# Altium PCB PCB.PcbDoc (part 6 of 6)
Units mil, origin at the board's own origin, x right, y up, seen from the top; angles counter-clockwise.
Board outline 7100 x 7000 mil, 4 copper layers (Top Layer, GND, VCC, Bottom Layer), stack 61.2 mil thick; 759 components, 507 nets, 2200 pads, 452 vias.
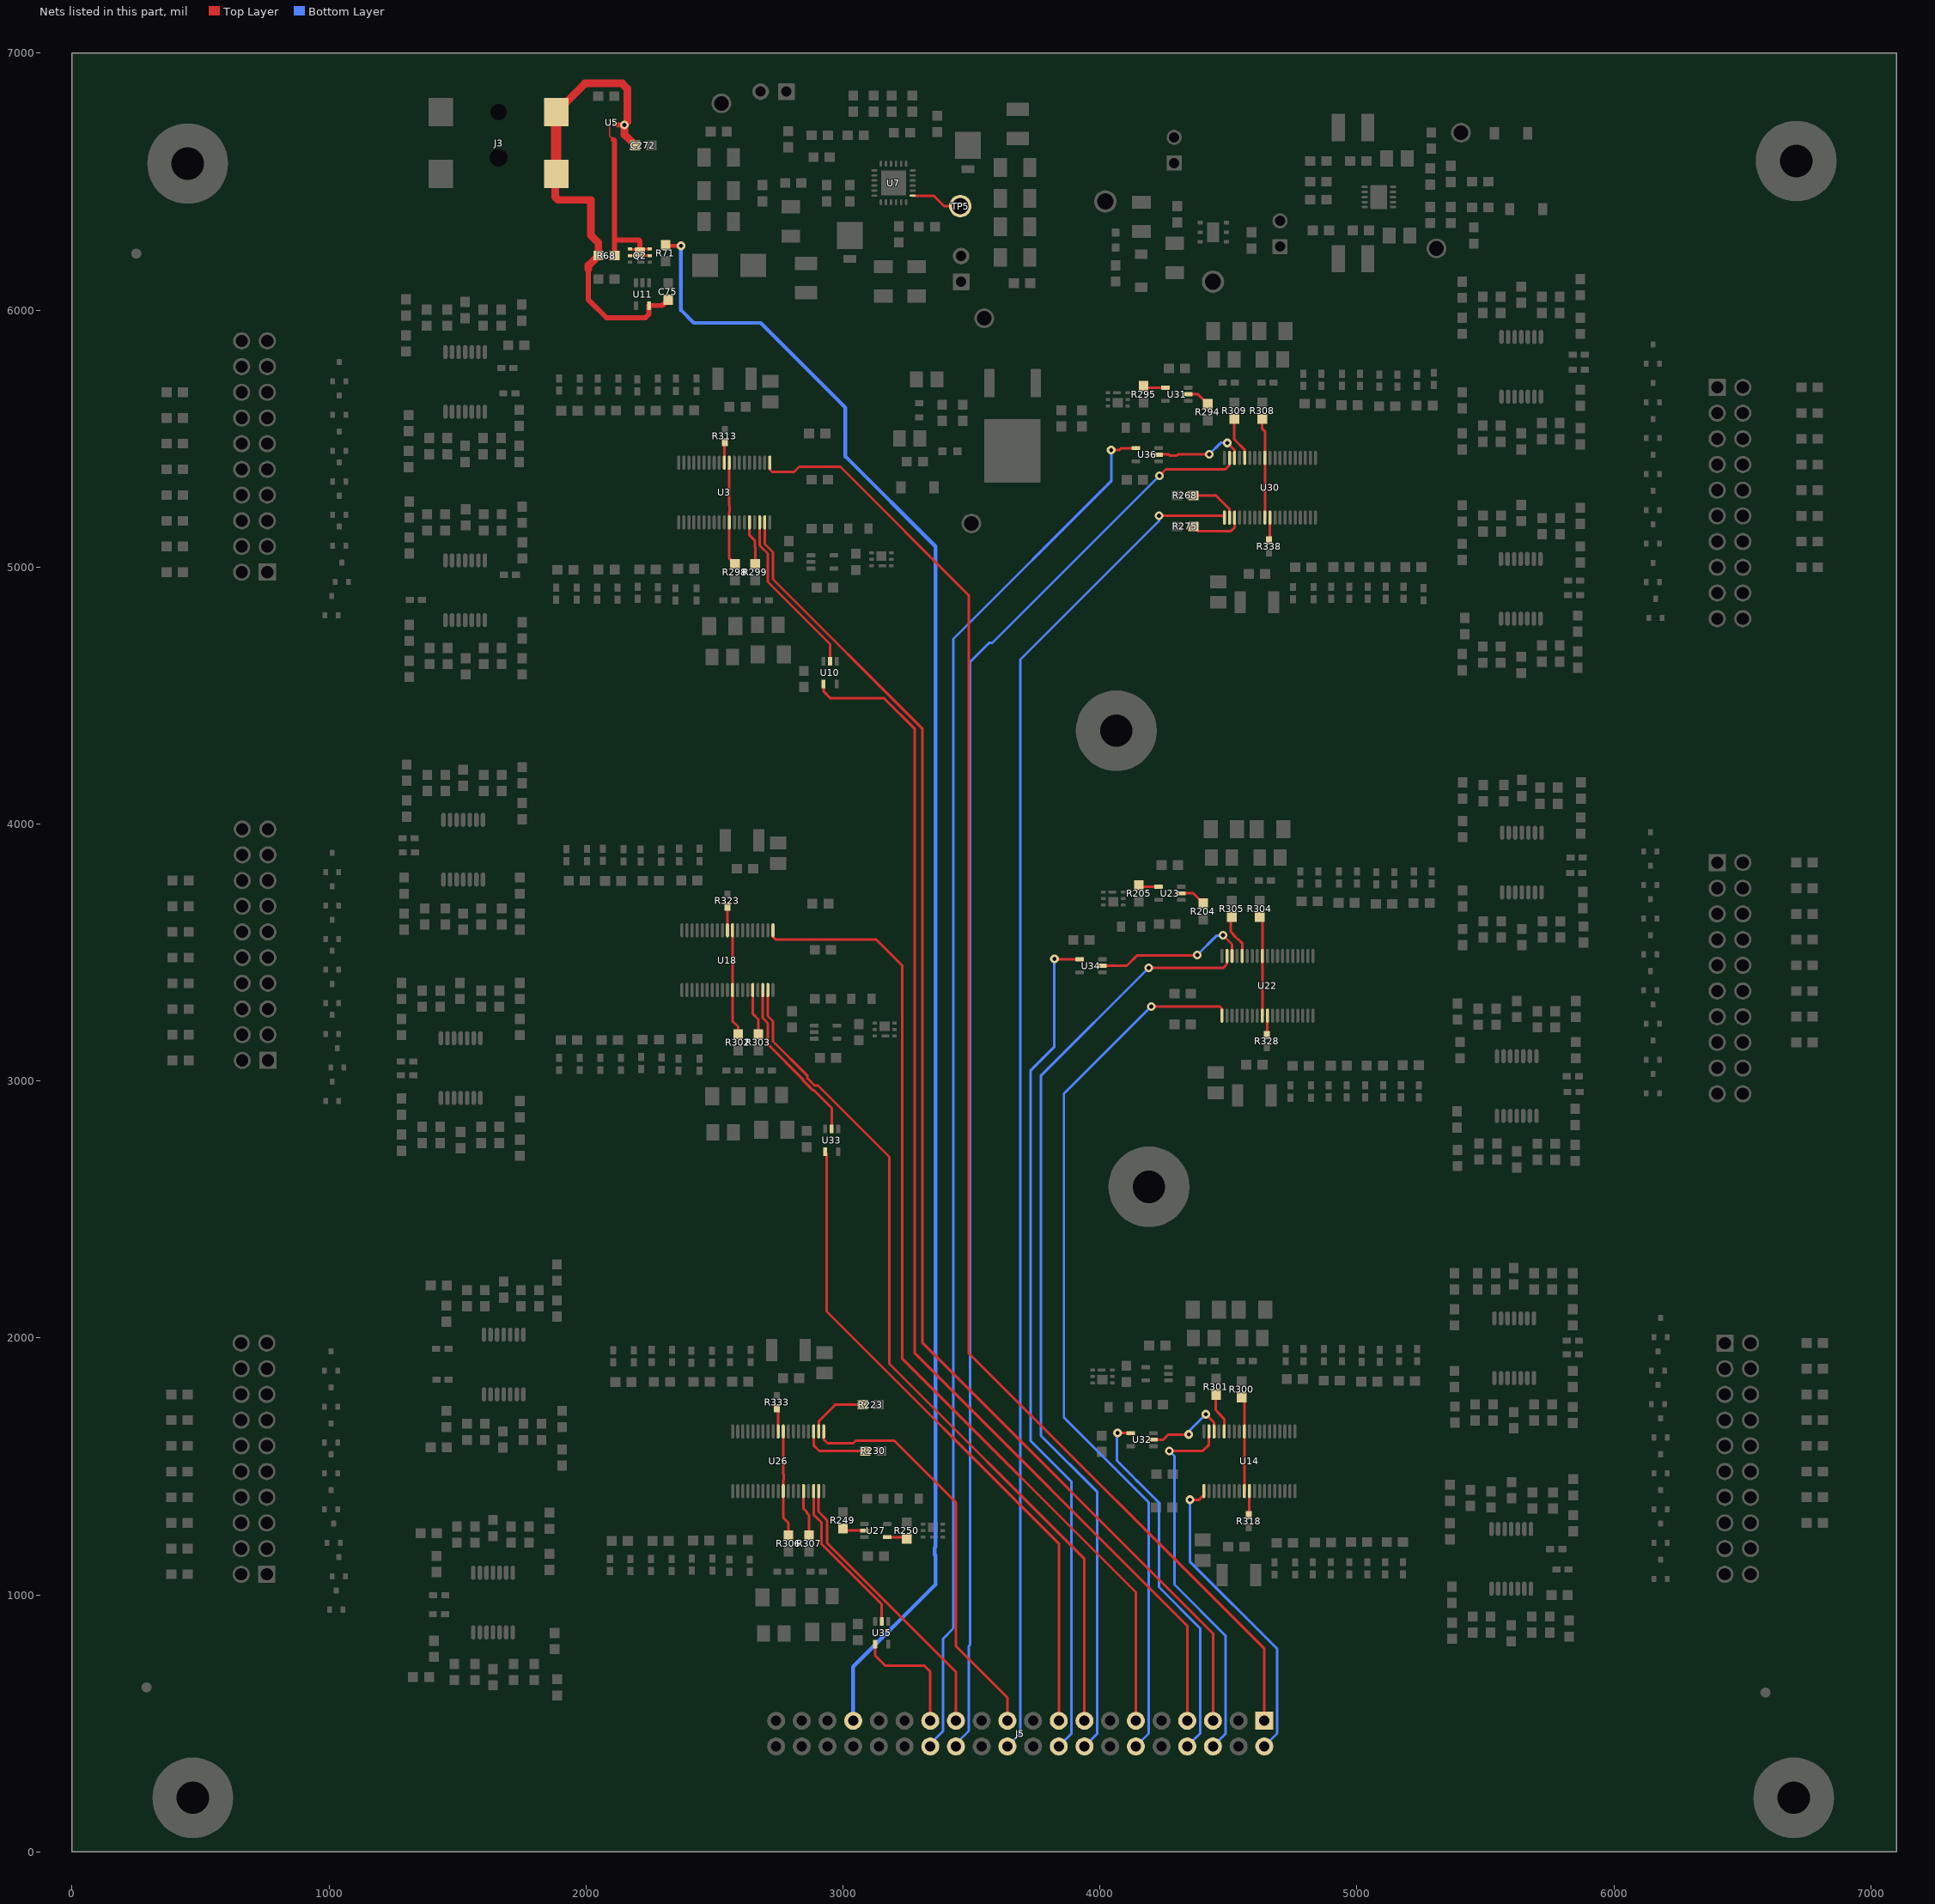
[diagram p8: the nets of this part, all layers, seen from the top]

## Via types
v1: diameter 34, hole 16, Top Layer to Bottom Layer, 440 vias
v2: diameter 19.68, hole 7.87, Top Layer to Bottom Layer, 11 vias
v3: diameter 30, hole 14, Top Layer to Bottom Layer, 1 vias

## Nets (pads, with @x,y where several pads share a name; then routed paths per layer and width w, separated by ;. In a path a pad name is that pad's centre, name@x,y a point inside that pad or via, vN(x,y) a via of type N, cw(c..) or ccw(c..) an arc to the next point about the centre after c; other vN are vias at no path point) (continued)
NetR204_2: R204.2 U23.2 | length 101.7
  Top Layer w10: U23.2@4316.34,3730 4363.55,3730 R204.2@4402.05,3691.5
NetR205_2: R205.2 U23.4 | length 78.2
  Top Layer w10: R205.2@4152.05,3761.5 4157.95,3755.59 U23.4@4227.75,3755.59
NetR223_1: R223.1 U26.2 | length 238.3
  Top Layer w10: U26.2@2905.74,1636.09 2906.64,1637 2906.64,1676.53 2968.26,1738.14 2968.26,1739.95 R223.1@3076.76,1739.95
NetR230_1: R230.1 U26.3 | length 263.8
  Top Layer w10: U26.3@2886.05,1636.09 2886.05,1582.16 2908.26,1559.95 R230.1@3086.76,1559.95
NetR249_2: R249.2 U27.2 | length 87.5
  Top Layer w10: R249.2@3000,1258.5 3008.5,1250 U27.2@3083.96,1250
NetR250_2: R250.2 U27.4 | length 78.2
  Top Layer w10: U27.4@3172.54,1224.41 3242.35,1224.41 R250.2@3248.25,1218.5
NetR268_1: R268.1 U30.2 | length 197.4
  Top Layer w10: R268.1@4363.39,5278.26 4448.26,5278.26 4450,5280 4504.41,5225.59 U30.2@4504.41,5192.44
NetR275_1: R275.1 U30.3 | length 212.5
  Top Layer w10: R275.1@4363.39,5158.26 4381.65,5140 4510,5140 4524.09,5154.09 U30.3@4524.09,5192.44
NetR294_2: R294.2 U31.2 | length 91.7
  Top Layer w10: U31.2@4344.29,5672.44 4381.5,5672.44 R294.2@4420,5633.94
NetR295_2: R295.2 U31.4 | length 88.2
  Top Layer w10: R295.2@4170,5703.94 4175.91,5698.03 U31.4@4255.71,5698.03
NetR298_1: R298.1 U3.9 U3.30 | length 404.6
  Top Layer w10: U3.9@2557.94,5406.14 2557.94,5240.31 2558.87,5239.37 2558.87,5238.12 2558.87,5214.63 2558.13,5213.88 2557.94,5213.69 U3.30@2557.94,5173.86 2557.94,5033.5 R298.1@2580,5011.45
NetR299_1: R299.1 U3.34 | length 172.7
  Top Layer w10: U3.34@2636.68,5173.86 2636.68,5123.32 2658.18,5101.82 2658.18,5076.54 2660,5074.72 2660,5013.24 R299.1@2658.26,5011.5
NetR300_1: R300.1 U14.9 U14.30 | length 369.5
  Top Layer w10: R300.1@4552.05,1768.5 4562.36,1758.19 U14.30@4562.36,1636.14 4562.36,1586.89 4562.87,1586.37 4562.87,1586.12 4562.87,1561.63 4562.13,1560.88 4562.13,1560.63 4562.36,1560.39 U14.9@4562.36,1403.86
NetR301_1: R301.1 U14.34 | length 157.1
  Top Layer w10: R301.1@4452.05,1778.5 4450,1776.46 4450,1720 4470.13,1699.87 4470.13,1697.63 4483.62,1684.13 U14.34@4483.62,1636.14
NetR302_1: R302.1 U18.9 U18.30 | length 414.2
  Top Layer w10: U18.9@2570.3,3586.09 2570.3,3424.94 2570.5,3424.75 2570.87,3424.37 2570.87,3399.63 2570.5,3399.25 2570.3,3399.06 U18.30@2570.3,3353.8 2570.3,3233.03 2592.36,3210.97 R302.1@2592.36,3181.45
NetR303_1: R303.1 U18.34 | length 181.2
  Top Layer w10: U18.34@2649.04,3353.8 2649.95,3352.9 2649.95,3260.05 2670.62,3239.38 R303.1@2670.62,3181.5
NetR304_1: R304.1 U22.9 U22.30 | length 388.6
  Top Layer w10: R304.1@4622.05,3638.5 4632.36,3628.19 U22.30@4632.36,3486.46 U22.9@4632.36,3254.17
NetR305_1: R305.1 U22.34 | length 172.8
  Top Layer w10: R305.1@4513.35,3638.5 4510,3635.16 4510,3580 4520.13,3569.87 4520.13,3567.63 4537.63,3550.13 4539.87,3550.13 4553.62,3536.38 U22.34@4553.62,3486.46
NetR306_1: R306.1 U26.9 U26.30 | length 415.8
  Top Layer w10: U26.9@2767.94,1636.09 2767.94,1474.67 2766.26,1472.99 2768.87,1470.37 2768.87,1445.63 2767.26,1444.01 2767.94,1443.31 U26.30@2767.94,1403.81 2767.94,1300.27 2788.26,1279.95 R306.1@2788.26,1231.45
NetR307_1: R307.1 U26.34 | length 181.3
  Top Layer w10: U26.34@2846.68,1403.81 2846.68,1335.57 2859.87,1322.37 2859.87,1318.33 2868.26,1309.95 R307.1@2868.26,1231.45
NetR308_1: R308.1 U30.9 U30.30 | length 389.2
  Top Layer w10: R308.1@4631.89,5576.77 4631.89,5538.11 4642.2,5527.8 U30.30@4642.2,5424.72 4642.2,5379.04 4642.5,5378.75 4642.87,5378.37 4642.87,5353.63 4642.5,5353.25 4642.2,5352.96 U30.9@4642.2,5192.44
NetR309_1: R309.1 U30.34 | length 168.7
  Top Layer w10: R309.1@4523.19,5576.77 4523.19,5498.06 4525.87,5495.37 4525.87,5494.13 4563.46,5456.54 U30.34@4563.46,5424.72
NetR313_2: R313.2 U3.10 | length 80
  Top Layer w10: U3.10@2538.26,5406.14 2538.26,5483.64 R313.2@2540,5485.38
NetR318_2: R318.2 U14.10 | length 93.9
  Top Layer w10: R318.2@4580,1310.81 4581.14,1311.95 4581.14,1402.95 U14.10@4582.05,1403.86
NetR323_2: R323.2 U18.10 | length 92.5
  Top Layer w10: R323.2@2550,3678.38 2550.62,3677.76 U18.10@2550.62,3586.09
NetR328_2: R328.2 U22.10 | length 76.4
  Top Layer w10: R328.2@4650,3178.62 4652.05,3180.67 U22.10@4652.05,3254.17
NetR333_2: R333.2 U26.10 | length 92.5
  Top Layer w10: R333.2@2743,1726.38 2748.26,1721.12 U26.10@2748.26,1636.09
NetR338_2: R338.2 U30.10 | length 90.4
  Top Layer w10: R338.2@4658,5103.62 4661.89,5107.51 U30.10@4661.89,5192.44
NetTP5_1: TP5.1 U7.7 | length 202.3
  Top Layer w10: U7.7@3271.73,6445.36 3352.89,6445.36 3393.93,6404.31 3456.68,6404.31 TP5.1@3456.93,6404.57
NetU3_36: U3.36 U10.2 | length 654
  Top Layer w10: U3.36@2676.05,5173.86 2676.05,5084.95 2677.86,5083.14 2677.86,5082.14 2707.5,5052.5 2707.5,4942.5 2950,4700 U10.2@2950,4633.29
NetU14_36: U14.36 U32.2 | length 332.5
  Top Layer w10: U32.2@4208.29,1604 4247,1604 4267,1624 v1(4346,1624) ; v1(4412,1703) 4444.25,1670.75 U14.36@4444.25,1636.14
  Bottom Layer w10: v1(4346,1624) 4346,1637 v1(4412,1703)
NetU18_36: U18.36 U33.2 | length 653.6
  Top Layer w10: U18.36@2688.41,3353.8 2688.41,3246.86 2688.49,3246.79 2688.49,3244.51 2708,3225 2708,3143 2844.38,3006.62 2844.38,3002.82 2882.82,2964.38 2886.62,2964.38 2956,2895 U33.2@2956,2813.29
NetU22_36: U22.36 U34.2 | length 616.1
  Top Layer w10: U34.2@4010.29,3448 4105,3448 4146,3489 4378,3489 v1(4379,3490) ; v1(4479,3567) 4514.25,3531.75 U22.36@4514.25,3486.46
  Bottom Layer w10: v1(4379,3490) 4455,3566 v1@4480,3566 ; v1(4479,3567) v1@4480,3566 ; v1@4481,3566 v1@4480,3566
NetU26_36: U26.36 U35.2 | length 616.3
  Top Layer w10: U26.36@2886.05,1403.81 2886.05,1317.43 2886.13,1317.35 2886.13,1312.87 2917,1282 2917,1206 2917,1197.72 3151,963.72 U35.2@3151,897.29
NetU30_36: U30.36 U36.2 | length 360.5
  Top Layer w10: U36.2@4229.29,5437 4231.29,5439 4267.75,5439 4273.63,5433.13 4298.37,5433.13 4304.25,5439 v1(4426,5439) ; v1(4496,5483) 4524.09,5454.91 U30.36@4524.09,5424.72
  Bottom Layer w10: v1(4426,5439) 4470,5483 v1(4496,5483)
OE: J5.33 R71.1 | length 6498.3
  Top Layer w15: R71.1@2310,6253.46 2313.46,6250 v1(2370,6250)
  Bottom Layer w15: v1(2370,6250) 2370,6000 2420,5950 2680,5950 3010,5620 3010,5430 3360,5080 3360,1185.78 3357.63,1183.41 3357.63,1156.59 3360,1154.22 3360,1040 3040,720 J5.33@3040,510
ON: Q2.1 Q2.2 Q2.5 Q2.6 Q2.8 R68.1 U5.B2 | length 807.9
  Top Layer w6: U5.B2@2092.13,6722.44 2092.13,6678.19 2106.16,6664.16
  Top Layer w10: Q2.2@2171.61,6211.97 2188.35,6211.97 2190,6210.31 ; Q2.1@2171.61,6237.56 2173.58,6235.59 2191.95,6235.59 2202.77,6224.76 Q2.8@2210,6224.76 ; Q2.5@2248.39,6211.97 2222.8,6211.97 Q2.8@2210,6224.76 ; Q2.6@2248.39,6237.56 2222.8,6237.56 Q2.8@2210,6224.76
  Top Layer w20: 2106.16,6664.16 2111.5,6658.82 R68.1@2111.5,6211.97 ; 2116,6273 2205,6273 2210,6268 Q2.8@2210,6224.76
SCLK_1: J5.5 U3.37 | length 5386.4
  Top Layer w10: U3.37@2695.74,5173.86 2695.74,5089.54 2727.87,5057.4 2727.87,4952.13 3310,4370 3310,1980 4440,850 J5.5@4440,510
SCLK_2: J5.6 U14.37 | length 1478.2
  Top Layer w10: v1(4270,1560) 4400,1560 4424.57,1584.57 U14.37@4424.57,1636.14
  Bottom Layer w10: v1(4270,1560) 4290,1540 4290,1040 4490,840 4490,460 J5.6@4440,410
SCLK_3: J5.15 U18.37 | length 3361.6
  Top Layer w10: U18.37@2708.1,3353.8 2708.1,3252.46 2727.87,3232.68 2727.87,3154.13 2862.25,3019.75 2862.25,3010.22 2890.22,2982.25 2903.03,2982.25 3181,2704.28 3181,1899 3940,1140 J5.15@3940,510
SCLK_4: J5.16 U22.37 | length 3658.3
  Top Layer w10: v1(4190,3440) 4480,3440 4494.57,3454.57 U22.37@4494.57,3486.46
  Bottom Layer w10: J5.16@3940,410 3990,460 3990,1400 3770,1620 3770,3020 v1(4190,3440)
SCLK_5: J5.25 U26.37 | length 1091.7
  Top Layer w10: U26.37@2904.83,1380 2904.83,1323.93 2937.87,1290.89 2937.87,1202.13 3440,700 J5.25@3440,510
SCLK_6: J5.26 U30.37 | length 5617.7
  Top Layer w10: v1@4238,5355 v1(4232,5355) 4257,5380 4488.21,5380 4503.5,5395.29 4503.5,5423.82 U30.37@4504.41,5424.72
  Bottom Layer w10: J5.26@3440,410 3440,420 3490,470 3490,800 3495,805 3495,4631 3569.13,4705.13 3582.13,4705.13 v1(4232,5355) v1@4219,5355
SDI_1: J5.1 U3.1 | length 5851.4
  Top Layer w10: U3.1@2714.52,5380 2724.52,5370 2810,5370 2830,5390 2990,5390 3490,4890 3490,1940 4640,790 J5.1@4640,510
SDI_2: J5.2 U14.1 | length 1199.5
  Top Layer w10: v1(4350,1370) 4386.46,1370 4404.88,1388.43 U14.1@4404.88,1403.86
  Bottom Layer w10: v1(4350,1370) 4350,1130 4690,790 4690,460 J5.2@4640,410
SDI_3: J5.11 U18.1 | length 3890.4
  Top Layer w10: U18.1@2727.79,3586.09 2727.79,3560.74 2738.53,3550 3130,3550 3230,3450 3230,1920 4140,1010 J5.11@4140,510
SDI_4: J5.12 U22.1 | length 3458.2
  Top Layer w10: v1(4200,3290) 4465.79,3290 U22.1@4475.79,3280
  Bottom Layer w10: J5.12@4140,410 4190,460 4190,1360 3860,1690 3860,2950 v1(4200,3290)
SDI_5: J5.21 U26.1 | length 1588.5
  Top Layer w10: U26.1@2925.42,1636.09 2925.42,1604.58 2940,1590 3040,1590 3050,1600 3200,1600 3440,1360 3440,800 3640,600 J5.21@3640,510
SDI_6: J5.22 U30.1 | length 5292.2
  Top Layer w10: v1(4230,5200) 4477.17,5200 U30.1@4484.72,5192.44
  Bottom Layer w10: J5.22@3640,410 3689.99,459.99 3689.99,4639.99 4230,5180 v1(4230,5200)
SDO_1: J5.7 U10.4 | length 4743.5
  Top Layer w10: U10.4@2924.41,4544.71 2924.41,4516.59 2952,4489 3161,4489 3280,4370 3280,1940 4340,880 J5.7@4340,510
SDO_2: J5.8 U32.4 | length 1437.4
  Top Layer w10: v1(4069,1630) 4110.12,1630 4115.12,1625 U32.4@4119.71,1629.59
  Bottom Layer w10: v1(4069,1630) 4066,1633 4066,1522.7 4130.13,1458.57 4130.13,1457.63 4147.63,1440.13 4148.57,1440.13 4230,1358.7 4230,1030 4390,870 4390,460 J5.8@4340,410
SDO_3: J5.17 U33.4 | length 2591.5
  Top Layer w10: U33.4@2930.41,2724.71 2937,2718.12 2937,2103 3840,1200 J5.17@3840,510
SDO_4: J5.18 U34.4 | length 3289.8
  Top Layer w10: v1(3823,3475) 3824.41,3473.59 U34.4@3921.71,3473.59
  Bottom Layer w10: v1(3823,3475) 3823,3133 3730,3040 3730,1600 3890,1440 3890,460 J5.18@3840,410
SDO_5: J5.27 U35.4 | length 476.6
  Top Layer w10: U35.4@3125.41,808.71 3125.41,763.59 3165,724 3317,724 3340,701 J5.27@3340,510
SDO_6: J5.28 U36.4 | length 5436.5
  Top Layer w10: v1(4044,5455) 4076,5455 4083.59,5462.59 U36.4@4140.71,5462.59
  Bottom Layer w10: J5.28@3340,410 3340,420 3390,470 3390,830 3430,870 3430,4720 4044,5334 v1(4044,5455)
V_IN: C75.1 C272.1 J3.1 J3.1A R68.2 U5.A2 U11.5 | length 1909.8
  Top Layer w6: U5.A2@2107.87,6722.44 v1@2137.87,6722.44
  Top Layer w20: 2010,6160 2010,6040 2080,5970 2231.18,5970 2245.59,5984.41 U11.5@2245.59,6017.68 2297.2,6017.68 C75.1@2320,6040.47 ; 2125,6720.32 v1(2150,6720.32)
  Top Layer w30: J3.1A@1884.41,6529.92 1880,6525.51 1880,6440 1891.18,6428.82 2020,6428.82 2020,6290.31 2048.5,6261.81 R68.2@2048.5,6211.97 2010,6173.46 2010,6160 ; J3.1@1884.41,6770.08 1996.33,6882 2141,6882 2161,6862 2161,6731.32 v1(2150,6720.32) 2150,6682.5 C272.1@2191.5,6641
  Top Layer w40: J3.1A@1884.41,6529.92 J3.1@1884.41,6770.08
pads on no net: FID1.1 FID2.1 FID3.1 H1.1 H2.1 H3.1 H4.1 H9.1 H10.1 H11.0 H12.0 J3.3 J3.MH1 J3.MH2 Q1.0 Q2.0 Q3.0 Q4.0 Q5.0 Q6.0 Q7.0 U3.35 U4.1 U6.5 U7.12 U7.20 U8.11@5075.55,6379.76 U8.11@5075.55,6500.24 U8.11@5085.39,6415.2 U8.11@5085.39,6464.8 U8.11@5095.24,6379.76 U8.11@5095.24,6500.24 U9.4@3581.46,5498.03 U9.4@3581.46,5544.49 U9.4@3633.82,5498.03 U9.4@3633.82,5544.49 U9.4@3686.18,5498.03 U9.4@3686.18,5544.49 U9.4@3738.54,5498.03 U9.4@3738.54,5544.49 U9.5 U9.6 U9.7 U10.1 U11.1 U14.35 U15.1 U18.35 U19.1 U22.35 U23.1 U26.35 U27.1 U30.35 U31.1 U32.1 U33.1 U34.1 U35.1 U36.1

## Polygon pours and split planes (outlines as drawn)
DGND on GND "GND_DGND_P002" (solid, remove dead copper, pour order 2): 3000,300 3100,200 4600,200 4700,300 4700,800 4360,1116 4359.04,1299.04 4350,1290 4359.04,1299.04 4370,1300 4450,1310 4470,1380 4470,1520 4500,1520 4500,2800 4400,2900 4400,3100 4540,3240 4540,3360 4570,3360 4570,4700 4400,4870 4400,5060 4550,5210 4550,5310 4580,5310 4566.69,5323.31 4566.69,5962.55 4547.45,5962.55 4566.69,5962.55 4520,6000 4250,6000 4060,6000 4000,5940 4000,5390 3810,5200 3330,5200 3290,5240 3290,5810 3200,5900 2840,5900 2770,5830 2770,5600 2650,5480 2650,5300 2620,5300 2610,5300 2610,5090 2620,5080 2620,4100 2800,3920 2800,3800 2660,3660 2660,3470 2630,3470 2620,3470 2620,3240 2630,3230 2640,3220 2640,2630 2640,2190 2750,2080 2890,2080 3020,1950 3020,1800 2980,1800 2860,1710 2860,1510 2820,1510 2820,1310 2820,1300 2830,1290 2840,1280 2840,750 2840,760 2850,750 2930,750 3000,680 3000,670 3000,290
AGND on GND "GND-No Net 1" (solid, remove dead copper, pour order 4): 300,200 6900,200 7000,300 7000,6700 6900,6800 6800,6900 300,6900 200,6800 200,300 300,200
+3.3V on VCC "VCC_+3.3V_P006" (solid, pour order 6): 2997.14,310 2997.14,347 3868,347 4697.14,347 4697.14,310 4697.14,810 4357.14,1126 4357.14,1220 4356.17,1309.04 4347.14,1300 4356.17,1309.04 4387.14,1310 4467.14,1390 4467.14,1530 4497.14,1530 4497.14,2810 4397.14,2910 4397.14,3110 4537.14,3250 4537.14,3370 4567.14,3370 4567.14,4710 4397.14,4880 4397.14,5070 4547.14,5220 4547.14,5320 4577.14,5320 4563.83,5333.31 4563.83,5972.55 4544.58,5972.55 4563.83,5972.55 4557.14,6010 4537.14,6010 4247.14,6010 4057.14,6010 3997.14,5950 3997.14,5400 3807.14,5210 3327.14,5210 3287.14,5250 3287.14,5820 3197.14,5910 2837.14,5910 2767.14,5840 2767.14,5610 2647.14,5490 2647.14,5310 2617.14,5310 2607.14,5310 2607.14,5100 2617.14,5090 2617.14,4110 2797.14,3930 2797.14,3810 2657.14,3670 2657.14,3480 2627.14,3480 2617.14,3480 2617.14,3250 2627.14,3240 2637.14,3230 2637.14,2640 2637.14,2200 2747.14,2090 2887.14,2090 3017.14,1960 3017.14,1810 2997.14,1810 2857.14,1670 2857.14,1520 2817.14,1520 2817.14,1320 2817.14,1310 2827.14,1300 2837.14,1290 2837.14,760 2837.14,770 2847.14,760 2927.14,760 2997.14,690 3087.14,600 2997.14,690 2997.14,300
+5V on VCC "VCC-No Net" (solid, remove dead copper, pour order 15): 2830,760 2780,710 2560,710 2540,710 2490,760 2500,770 2500,2600 2350,2750 2370,2770 2370,6100 2370,6147.99 2520,6297.99 2522.01,6300 3800,6300 4620,6300 4870,6050 4864.65,6044.65 4864.65,5308.58 4864.65,3464.65 4860,3460 4860,2820 4810,2770 4810,850 4720,760 4620,760 4620,250 4620,340 3106,340 3110,740 3100,750 3090,760
+12V on VCC "Top Layer-No Net 1" (solid, pour order 17): 330,800 963,200 6257,199 6900,870 6900,6130 6910,6140 6240,6810 4870,6817 4662,6472 860,6472 340,6200 330,6190
+5V_IN on VCC "VCC-No Net 1" (solid, pour order 25): 2090,6512 2090,6841 2140,6891 2146,6885 3523,6885 3524,6885 3561,6848 4845,6847 4702,6604 4638,6499 3564,6511 4638,6499 3532,6479 3527,6484 2137,6484 2118,6484
-12V on Bottom Layer "Top Layer-No Net 2" (solid, pour order 21): 2970,270 2970,665.95 2974,669.95 2963.04,680.91 2507.34,680.91 2507.34,692.66 2450,750 2470.64,770.64 2470.64,2593.31 2470.64,2599.32 2319.04,2750.92 2344.51,2776.39 2344.51,3321.18 2344.51,6154.98 2338.54,6160.94 2502.17,6324.57 2516.93,6324.57 4631.48,6324.57 4638.02,6318.02 4910.96,6045.08 4910.96,6040.92 4900.92,6040.92 4890,6030 4883.55,6023.55 4883.55,2810.25 4883.55,2803.55 4840,2760 4835.49,2755.49 4835.49,850 4835.49,845.49 4730,740 4712.58,722.58 4712.58,270 6300,270 6900,870 6900,6150 6899.95,6150.05 6240,6810 950,6810 330,6190 330,801.13 860,271.13 860,270 2987.42,270 2989.33,271.91 2989.33,274.62
NetD15_1 on Top Layer "Top Layer-No Net" (solid, pour order 29): 3221.78,6557.8 3221.78,6589.78 3232,6600 3236,6604 3423,6604 3423,6605 3442,6624 3443,6623 3473,6623 3473,6585 3469,6581 3447,6559 3437,6559 3222.98,6559 3221.78,6557.8

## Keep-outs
Keep-Out Layer:
  text ".Layer_Name" at 577,-858.49 h60

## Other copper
Top Layer:
  rectangle net AGND: 4647,3530 4678,3556
  rectangle net AGND: 4588,3529 4619,3555
  text ".Layer_Name" at 577,-858.49 h60
Bottom Layer:
  text ".Layer_Name" at 577,-858.49 h60

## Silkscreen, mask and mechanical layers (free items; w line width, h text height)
Top Overlay:
  region: 2680,210 2380,210 2380,110 2680,110
  text "+14V" at 4366,6628 h60
  text "+5.5V IN" at 986,6627 h60
  text "ONE" at 621,6118 h60
  text "-14V" at 4620,6096 h60
  text "SIX" at 6376,5929 h60
  text "THREE" at 547,4233 h60
  text "FOUR" at 6343,4087 h60
  text "TWO" at 6401,2217 h60
  text "FIVE" at 602,2215 h60
  text "'.PRJ_Number'.PCB_Rev-" at 1845,125.77 h108.27
  text ".Layer_Name" at 577,-858.49 h60
Bottom Overlay:
  text ".Layer_Name" at 577,-858.49 h60
Top Paste:
  text ".Layer_Name" at 577,-858.49 h60
Bottom Paste:
  text ".Layer_Name" at 577,-858.49 h60
Top Solder:
  text ".Layer_Name" at 577,-858.49 h60
  text ".Layer_Name" at 577,-858.49 h60
Bottom Solder:
  text ".Layer_Name" at 577,-858.49 h60
Drill Guide:
  text ".Layer_Name" at 577,-858.49 h60
M1 Board Outline:
  the board outline again, w10
  text ".Layer_Name" at 577,-858.49 h60
M2 Board Dimensions:
  rectangle: 125,-400 500,-275
  rectangle: 0,-275 125,-150
  lines w7: 0,-275 1000,-275 ; 125,-400 125,-150 ; 250,-400 250,-150 ; 500,-400 500,-150 ; 750,-400 750,-150 ; 0,-400 0,-150 1000,-150 1000,-400 0,-400
  text ".Layer_Name" at 577,-858.49 h60
M3 3D STEP Top:
  text ".Layer_Name" at 577,-858.49 h60
M4 3D STEP Bottom:
  text ".Layer_Name" at 577,-858.49 h60
M5 Assembly Top:
  lines w10: -292,-930.17 6308,-930.17 ; -292,-726.83 6310,-726.83 ; -292,-523.5 -292,-1133.5 3713,-1133.5 6310,-1133.5 6310,-523.5 -291.5,-523.5 -291.5,-1133.5 1284,-1133.5 ; 2173,-1133.5 2173,-523.5 ; 3440,-726.83 3440,-523.5 ; 4280,-726.83 4280,-523.5 ; 4902,-1140 4902,-937.17
  text "COMPONENTS MARKED 'DNP' SHOULD NOT BE POPULATED." at 1153.5,-318.5 h60
  text "ASSEMBLY VARIANT:" at 1153,-434 h60
  text ".VariantName" at 2189,-434 h60
  text "PCB VIEWED FROM TOP SIDE" at -228.5,-655.67 h60
  text "BOARD #:" at 2248,-655.67 h60
  text ".PRJ_Number" at 2793.5,-655.67 h60
  text "REV:" at 3638,-655.67 h60
  text ".PCB_Rev" at 3929.5,-655.67 h60
  text "SVN REV:" at 4476,-655.67 h60
  text ".VersionControl_RevNumber" at 4982,-655.67 h60
  text "TID #:" at 2248,-859 h60
  text ".TID" at 2793.5,-859 h60
  text "PLOT NAME =" at -228.5,-1064.34 h60
  text ".plot_File_Name" at 577,-1064.34 h60
  text "GENERATED    :" at 2250,-1064.34 h60
  text ".Print_Date" at 3119.5,-1064.34 h60
  text ".Print_Time" at 3848.5,-1064.34 h60
  text "TEXAS INSTRUMENTS" at 5113,-1064.34 h60
M6 Assembly Bottom:
  lines w10: -292.5,-727.33 6309.5,-727.33 ; -290.5,-930.67 6309.5,-930.67 ; 1115.5,-1140.5 1115.5,-937.67 ; 1737.5,-727.33 1737.5,-524 ; 2577.5,-727.33 2577.5,-524 ; 3844.5,-1134 3844.5,-524 ; 4733.5,-1134 6309,-1134 6309,-524 -292.5,-524 -292.5,-1134 2304.5,-1134 6309.5,-1134 6309.5,-524
  text "COMPONENTS MARKED 'DNP' SHOULD NOT BE POPULATED." at 6102,-318 h60
  text ".VariantName" at 5058,-434 h60
  text "ASSEMBLY VARIANT:" at 6097,-434 h60
  text ".VersionControl_RevNumber" at 1035.5,-656.17 h60
  text "SVN REV:" at 1541.5,-656.17 h60
  text ".PCB_Rev" at 2088,-656.17 h60
  text "REV:" at 2379.5,-656.17 h60
  text ".PRJ_Number" at 3224,-656.17 h60
  text "BOARD #:" at 3769.5,-656.17 h60
  text "PCB VIEWED FROM BOTTOM SIDE" at 6246,-656.17 h60
  text ".TID" at 3224,-859.5 h60
  text "TID #:" at 3769.5,-859.5 h60
  text "TEXAS INSTRUMENTS" at 904.5,-1064.84 h60
  text ".Print_Time" at 2169,-1064.84 h60
  text ".Print_Date" at 2898,-1064.84 h60
  text "GENERATED    :" at 3767.5,-1064.84 h60
  text ".plot_File_Name" at 5440.5,-1064.84 h60
  text "PLOT NAME =" at 6246,-1064.84 h60
M9 Title Sheet:
  drawing of 57 lines, arcs and shapes, not listed
  text "1" at 739.84,8036.5 h70
  text "2" at 3235.5,8036.5 h70
  text "3" at 5724.84,8036.5 h70
  text "4" at 8231.51,8036.5 h70
  text "5" at 10730.5,8036.5 h70
  text "6" at 13235.5,8036.5 h70
  text "A" at -416.5,6893.5 h70
  text "A" at 14383.5,6893.5 h70
  text "B" at -416.5,4513.5 h70
  text "B" at 14383.5,4513.5 h70
  text "C" at -416.5,2138.5 h70
  text "C" at 14383.5,2138.5 h70
  text "PROJECT TITLE:" at 11343.5,277.5 h45
  text ".PRJ_Title" at 11393.5,144.17 h70
  text "DESIGNED FOR:" at 11343.5,-23.5 h45
  text ".PRJ_Customer" at 11393.5,-163.5 h70
  text "D" at -416.5,-231.5 h70
  text "D" at 14383.5,-231.5 h70
  text "FILE NAME:" at 11343.5,-323.5 h45
  text ".PCB_File_Name_No_Path" at 11393.5,-443.5 h70
  text "Texas Instruments (TI) and/or its licensors do not warrant the accuracy or completeness of this specification" at 6374,-605.34 h45
  text "ENGINEER:" at 11343.5,-613.5 h45
  text "LAYOUT BY:" at 12848.5,-613.5 h45
  text "or any information contained therein. TI and/or its licensors do not warrant that this design will meet" at 6329.01,-718 h45
  text ".PRJ_Engineer" at 11393.5,-768.49 h70
  text ".PCB_Layout" at 12899,-768.49 h70
  text "the specifications, will be suitable for your application or fit for any particular purpose, or will operate in" at 6329.01,-830.67 h45
  text ".Layer_Name" at 577,-858.49 h60
  text "ALTIUM DESIGNER VERSION:" at 12848.5,-923.5 h45
  text "an implementation. TI and/or its licensors do not warrant that the design is production worthy. You should" at 6329.01,-943.33 h45
  text "completely validate and test your design implementation to confirm the system functionality for your application." at 6374,-1056 h45
  text ".print_Scale" at 11393.5,-1056.83 h70
  text ".Application_BuildNumber" at 12899,-1056.83 h70
  text "1" at 739.84,-1263.5 h70
  text "2" at 3235.5,-1263.5 h70
  text "3" at 5724.84,-1263.5 h70
  text "4" at 8231.51,-1263.5 h70
  text "5" at 10730.5,-1263.5 h70
  text "6" at 13235.5,-1263.5 h70
M10 Fab Notes:
  drawing of 173 lines, arcs and shapes, not listed
  text "DESIGN INFORMATION" at 12378.02,6201 h60
  text "MIN. TRACK WIDTH:" at 11733.46,6021 h60
  text "8" at 12829.7,6021 h60
  text "MIL" at 12984.46,6021 h60
  text "MIN. CLEARANCE:" at 11733.46,5889 h60
  text "0.2" at 12769.7,5889 h60
  text "mm" at 12984.46,5889 h60
  text "MIN. VIA PAD SIZE:" at 11733.46,5757 h60
  text "24" at 12799.71,5757 h60
  text "MIL" at 12984.46,5757 h60
  text "0.05mm (2MIL)" at 12428.46,5615.29 h60
  text "MINIMUM ANNULAR RING" at 11404.23,5611 h60
  text "EXTERNAL" at 13136.46,5611 h60
  text "PER" at 11604.23,5493 h60
  text "IPC-D-275 CLASS 2 LEVEL C" at 11824.23,5493 h60
  text "MIL, HOLES" at 13312.46,5380.71 h60
  text "+/-" at 12920,5380 h60
  text "+/-" at 13774,5380 h60
  text "REGISTRATION TOLERANCES:" at 11404.23,5375 h60
  text "METAL" at 12604,5375 h60
  text "5" at 13180.2,5375 h60
  text "3" at 14013.2,5375 h60
  text "MIL" at 14129.46,5375 h60
  text "+/-" at 13774,5262 h60
  text "HOLE SIZE TOLERANCE (UNLESS OTHERWISE SPECIFIED):" at 11404.23,5257 h60
  text "3" at 14013.2,5257 h60
  text "MIL" at 14129.46,5257 h60
  text "MATERIAL:" at 11329.46,5047.54 h60
  text "FR-4 High Tg" at 12315.9,4907.21 h60
  text "FR-408" at 11750.46,4898.64 h60
  text "OTHER" at 13238.46,4898.64 h60
  text "X" at 12161,4895 h60
  text "62 MIL (1.6mm) +/-10%" at 12070.56,4735.92 h60
  text "THICKNESS:" at 11404.23,4731.64 h60
  text "X" at 11942.4,4731.64 h60
  text "OTHER" at 13355.46,4731.64 h60
  text "TOLERANCE:" at 11404.23,4573.64 h60
  text "X" at 12243.53,4573.64 h60
  text "ANSI IPC-6012 TYPE 3 CLASS 2" at 12430.48,4573.64 h60
  text "OTHER +/-" at 12430.46,4417.64 h60
  text "BOW & TWIST:" at 11404.23,4260.64 h60
  text "X" at 12243.53,4260.64 h60
  text "ANSI IPC-6012 TYPE 3 CLASS 2" at 12430.48,4260.64 h60
  text "OTHER +/-" at 12430.46,4102.13 h60
  text "DRILLING:" at 11329.46,3963.64 h60
  text "REFERENCE:" at 11404.23,3846.64 h60
  text "X" at 12052.46,3846.64 h60
  text "AS SHOWN" at 12239.46,3846.64 h60
  text "X" at 12953.46,3846.64 h60
  text "NC_DRILL FILES" at 13090.46,3846.64 h60
  text "PTH COPPER THICKNESS:" at 11404.23,3688.64 h60
  text "X" at 12534.46,3688.64 h60
  text "20-30 um" at 12671.46,3688.64 h60
  text "OTHER" at 13388.46,3688.64 h60
  text "BOARD FINISH:" at 11329.46,3529.64 h60
  text "SILKSCREEN:" at 11484.68,3411.64 h60
  text "X" at 12433.46,3411.64 h60
  text "TOP" at 12559.46,3411.64 h60
  text "X" at 12943.46,3411.64 h60
  text "BOTTOM" at 13070.46,3411.64 h60
  text "SILKSCREEN COLOR:" at 11484.68,3244.64 h60
  text "X" at 12432.42,3244.64 h60
  text "WHITE" at 12559.46,3244.64 h60
  text "OTHER" at 13070.46,3244.64 h60
  text "X" at 12563.42,3085.44 h60
  text "GREEN" at 12690.46,3085.44 h60
  text "OTHER" at 13308.46,3085.44 h60
  text "SOLDER RESIST COLOR:" at 11484.68,3074.64 h60
  text "X" at 12563.42,2915.44 h60
  text "MATTE" at 12690.46,2915.44 h60
  text "SEMI-GLOSS" at 13308,2914.8 h60
  text "IMMERSION GOLD (ENIG)" at 12390.46,2726.92 h60
  text "ENEPIG" at 13728,2723.64 h60
  text "SURFACE FINISH:" at 11329.46,2722.64 h60
  text "X" at 12203.51,2722.64 h60
  text "IMM. TIN/SILVER OR EQUIV" at 11659,2565.64 h60
  text "OTHER" at 13090.46,2565.64 h60
  text "ARRAY/PANEL:" at 11329.46,2386.64 h60
  text "CUT AND TRIM PER M1 BOARD OUTLINE" at 12390.46,2382.35 h60
  text "N.C. ROUTE" at 12390.46,2230.64 h60
  text "X" at 13069.46,2230.64 h60
  text "V. SCORE" at 13256.46,2230.64 h60
  text "CERTIFICATION:" at 11329.46,2093.64 h60
  text "MATERIALS AND WORKMANSHIP FOR ALL PCBS" at 12054.46,2093.64 h60
  text "TO MEET OR EXCEED THE REQUIREMENTS OF:" at 12054.46,1995.64 h60
  text "X" at 11680.96,1859.13 h60
  text "ANSI IPC-A-600F CLASS ->" at 11819.96,1859.13 h60
  text "X" at 13459.02,1859.13 h60
  text "2" at 13577.96,1859.14 h60
  text "1" at 13262.96,1857.64 h60
  text "3" at 13931.96,1857.64 h60
  text "X" at 12495.02,1699.64 h60
  text "RoHS" at 12631.96,1699.64 h60
  text "OTHER" at 13276.36,1699.64 h60
  text "PER ORDER" at 13673.42,1699.64 h60
  text "ALL BOARDS MUST MEET OR EXCEED UL94-V0 REQUIREMENTS." at 11357,1534 h60
  text "PCB MUST BEAR THE UL94V-0 UL REGISTERED MATERIAL ID NUMBER" at 11357,1414 h60
  text "ADDITIONAL REQUIREMENTS:" at 11329.46,1240.64 h60
  text "MICROSECTION:" at 11404.23,1125.64 h60
  text "YES" at 12309.96,1125.64 h60
  text "REQUIRED" at 13171.46,969.49 h60
  text "BARE BOARD ELEC. TEST:" at 11404.23,966.64 h60
  text "NONE" at 12709.96,966.64 h60
  text "X" at 13044.46,966.64 h60
  text "PER ORDER" at 13763.46,966.64 h60
  text ".Layer_Name" at 577,-858.49 h60
M11 Gerber Information:
  lines w10: -292,-930.17 6308,-930.17 ; -292,-726.83 6310,-726.83 ; -292,-523.5 -292,-1133.5 3713,-1133.5 6310,-1133.5 6310,-523.5 -291.5,-523.5 -291.5,-1133.5 1284,-1133.5 ; 2173,-1133.5 2173,-523.5 ; 3440,-726.83 3440,-523.5 ; 4280,-726.83 4280,-523.5 ; 4902,-1140 4902,-937.17
  text "ALL ARTWORK VIEWED FROM TOP SIDE" at -228.5,-655.67 h60
  text "BOARD #:" at 2248,-655.67 h60
  text ".PRJ_Number" at 2793.5,-655.67 h60
  text "REV:" at 3638,-655.67 h60
  text ".PCB_Rev" at 3929.5,-655.67 h60
  text "SVN REV:" at 4476,-655.67 h60
  text ".VersionControl_RevNumber" at 4982,-655.67 h60
  text "LAYER NAME =" at -228.5,-858.49 h60
  text "TID #:" at 2248,-859 h60
  text ".TID" at 2793.5,-859 h60
  text "PLOT NAME =" at -228.5,-1064.34 h60
  text ".plot_File_Name" at 577,-1064.34 h60
  text "GENERATED    :" at 2250,-1064.34 h60
  text ".Print_Date" at 3119.5,-1064.34 h60
  text ".Print_Time" at 3848.5,-1064.34 h60
  text "TEXAS INSTRUMENTS" at 5113,-1064.34 h60
M12 Stackup:
  drawing of 191 lines, arcs and shapes, not listed
  text "Layer" at 9790.34,7830 h60
  text "Name" at 10200.26,7830 h60
  text "Material" at 11130,7830 h60
  text "Thickness" at 11989.77,7830 h60
  text "Constant" at 12639.6,7830 h60
  text "Board Layer Stack" at 13209.46,7830 h60
  text "1" at 9790.34,7710 h60
  text "Top Overlay" at 10200.26,7710 h60
  text "2" at 9790.34,7590 h60
  text "Top Solder" at 10200.26,7590 h60
  text "Solder Resist" at 11130,7590 h60
  text "0.40mil" at 11989.77,7590 h60
  text "3.5" at 12639.6,7590 h60
  text "3" at 9790.34,7470 h60
  text "Top Layer" at 10200.26,7470 h60
  text "Copper" at 11130,7470 h60
  text "1.40mil" at 11989.77,7470 h60
  text "4" at 9790.34,7350 h60
  text "Dielectric1" at 10200.26,7350 h60
  text "FR-4" at 11130,7350 h60
  text "59.20mil" at 11989.77,7350 h60
  text "4.8" at 12639.6,7350 h60
  text "5" at 9790.34,7230 h60
  text "Bottom Layer" at 10200.26,7230 h60
  text "Copper" at 11130,7230 h60
  text "1.40mil" at 11989.77,7230 h60
  text "6" at 9790.34,7110 h60
  text "Bottom Solder" at 10200.26,7110 h60
  text "Solder Resist" at 11130,7110 h60
  text "0.40mil" at 11989.77,7110 h60
  text "3.5" at 12639.6,7110 h60
  text "7" at 9790.34,6990 h60
  text "Bottom Overlay" at 10200.26,6990 h60
  text ".Layer_Name" at 577,-858.49 h60
M13 Component Bodies Top:
  text ".Layer_Name" at 577,-858.49 h60
M14 Component Bodies Bottom:
  text ".Layer_Name" at 577,-858.49 h60
M15 Courtyards Top:
  text ".Layer_Name" at 577,-858.49 h60
M16 Courtyards Bottom:
  text ".Layer_Name" at 577,-858.49 h60
Drill Drawing:
  circle w10: c7781.46,5279.42 r27.73
  lines w10: 7753.73,5376.46 7781.46,5390.33 7809.19,5376.46 7795.32,5404.19 7809.19,5431.92 7781.46,5418.05 7753.73,5431.92 7767.6,5404.19 7753.73,5376.46 ; 7753.73,5528.96 7781.46,5501.23 7809.19,5528.96 7781.46,5556.68 7753.73,5528.96 ; 7753.73,5639.86 7767.6,5639.86 7767.6,5626 7795.32,5626 7795.32,5639.86 7809.19,5639.86 7809.19,5667.59 7795.32,5667.59 7795.32,5681.45 7767.6,5681.45 7767.6,5667.59 7753.73,5667.59 7753.73,5639.86 ; 7753.73,5750.77 7809.19,5750.77 7809.19,5806.22 7753.73,5806.22 7753.73,5750.77 ; 7753.73,5875.54 7809.19,5875.54 7809.19,5930.99 7753.73,5930.99 7753.73,5875.54 ; 7753.73,6000.3 7781.46,6014.17 7809.19,6000.3 7795.32,6028.03 7809.19,6055.76 7781.46,6041.89 7753.73,6055.76 7767.6,6028.03 7753.73,6000.3 ; 7753.73,6125.07 7753.73,6138.94 7767.6,6152.8 7753.73,6166.66 7753.73,6180.52 7767.6,6180.52 7781.46,6166.66 7795.32,6180.52 7809.19,6180.52 7809.19,6166.66 7795.32,6152.8 7809.19,6138.94 7809.19,6125.07 7795.32,6125.07 7781.46,6138.94 7767.6,6125.07 7753.73,6125.07 ; 7753.73,6305.29 7809.19,6305.29 7781.46,6249.84 7753.73,6305.29 ; 7753.73,6388.47 7767.6,6388.47 7781.46,6374.61 7795.32,6388.47 7809.19,6388.47 7795.32,6402.33 7809.19,6416.2 7795.32,6416.2 7781.46,6430.06 7767.6,6416.2 7753.73,6416.2 7767.6,6402.33 7753.73,6388.47 ; 7764.82,5886.63 7798.09,5886.63 7798.09,5919.9 7764.82,5919.9 7764.82,5886.63 ; 7764.82,6011.39 7781.46,6019.71 7798.09,6011.39 7789.78,6028.03 7798.09,6044.67 7781.46,6036.35 7764.82,6044.67 7773.14,6028.03 7764.82,6011.39
  lines w12: 7703.47,5214.27 10948.39,5214.27 ; 7703.47,6461.95 10948.39,6461.95 ; 8042.76,5089.5 8042.76,6586.71 ; 8376.19,5089.5 8376.19,6586.71 ; 9015.55,5089.5 9015.55,6586.71 ; 9275.79,5089.5 9275.79,6586.71 ; 9652.57,5089.5 9652.57,6586.71 ; 10379.51,5089.5 10379.51,6586.71 ; 7703.47,5089.5 10948.39,5089.5 10948.39,6586.71 7703.47,6586.71 7703.47,5089.5
  text "Symbol" at 7778.33,6499.38 h72.28
  text "Quantity" at 8080.19,6499.38 h72.28
  text "Finished Hole Size" at 8413.62,6499.38 h72.28
  text "Plated" at 9052.98,6499.38 h72.28
  text "Hole Type" at 9313.22,6499.38 h72.28
  text "Drill Layer Pair" at 9690,6499.38 h72.28
  text "Hole Tolerance" at 10416.94,6499.38 h72.28
  text "1" at 8080.19,6374.61 h60.23
  text "62.99mil (1.600mm)" at 8413.62,6374.61 h60.23
  text "NPTH" at 9052.98,6374.61 h60.23
  text "Round" at 9313.22,6374.61 h60.23
  text "Top Layer - Bottom Layer" at 9690,6374.61 h60.23
  text "1" at 8080.19,6249.84 h60.23
  text "70.87mil (1.800mm)" at 8413.62,6249.84 h60.23
  text "NPTH" at 9052.98,6249.84 h60.23
  text "Round" at 9313.22,6249.84 h60.23
  text "Top Layer - Bottom Layer" at 9690,6249.84 h60.23
  text "11" at 8080.19,6125.07 h60.23
  text "7.87mil (0.200mm)" at 8413.62,6125.07 h60.23
  text "PTH" at 9052.98,6125.07 h60.23
  text "Round" at 9313.22,6125.07 h60.23
  text "Top Layer - Bottom Layer" at 9690,6125.07 h60.23
  text "1" at 8080.19,6000.3 h60.23
  text "14.00mil (0.356mm)" at 8413.62,6000.3 h60.23
  text "PTH" at 9052.98,6000.3 h60.23
  text "Round" at 9313.22,6000.3 h60.23
  text "Top Layer - Bottom Layer" at 9690,6000.3 h60.23
  text "440" at 8080.19,5875.54 h60.23
  text "16.00mil (0.406mm)" at 8413.62,5875.54 h60.23
  text "PTH" at 9052.98,5875.54 h60.23
  text "Round" at 9313.22,5875.54 h60.23
  text "Top Layer - Bottom Layer" at 9690,5875.54 h60.23
  text "48" at 8080.19,5750.77 h60.23
  text "40.00mil (1.016mm)" at 8413.62,5750.77 h60.23
  text "PTH" at 9052.98,5750.77 h60.23
  text "Round" at 9313.22,5750.77 h60.23
  text "Top Layer - Bottom Layer" at 9690,5750.77 h60.23
  text "120" at 8080.19,5626 h60.23
  text "47.24mil (1.200mm)" at 8413.62,5626 h60.23
  text "PTH" at 9052.98,5626 h60.23
  text "Round" at 9313.22,5626 h60.23
  text "Top Layer - Bottom Layer" at 9690,5626 h60.23
  text "5" at 8080.19,5501.23 h60.23
  text "57.00mil (1.448mm)" at 8413.62,5501.23 h60.23
  text "PTH" at 9052.98,5501.23 h60.23
  text "Round" at 9313.22,5501.23 h60.23
  text "Top Layer - Bottom Layer" at 9690,5501.23 h60.23
  text "3" at 8080.19,5376.46 h60.23
  text "63.00mil (1.600mm)" at 8413.62,5376.46 h60.23
  text "PTH" at 9052.98,5376.46 h60.23
  text "Round" at 9313.22,5376.46 h60.23
  text "Top Layer - Bottom Layer" at 9690,5376.46 h60.23
  text "6" at 8080.19,5251.7 h60.23
  text "125.98mil (3.200mm)" at 8413.62,5251.7 h60.23
  text "PTH" at 9052.98,5251.7 h60.23
  text "Round" at 9313.22,5251.7 h60.23
  text "Top Layer - Bottom Layer" at 9690,5251.7 h60.23
  text "636 Total" at 8080.19,5126.93 h60.23
  text ".Layer_Name" at 577,-858.49 h60
M17 Embedded Cavity:
  text ".Layer_Name" at 577,-858.49 h60
M18 Embedded Assembly:
  text ".Layer_Name" at 577,-858.49 h60
M19 Embedded Keepout:
  text ".Layer_Name" at 577,-858.49 h60

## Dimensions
0,0 to 7100,0 on M2 Board Dimensions
0,0 to 0,7000 on M2 Board Dimensions
0,-400 to 1000,-400 on M2 Board Dimensions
